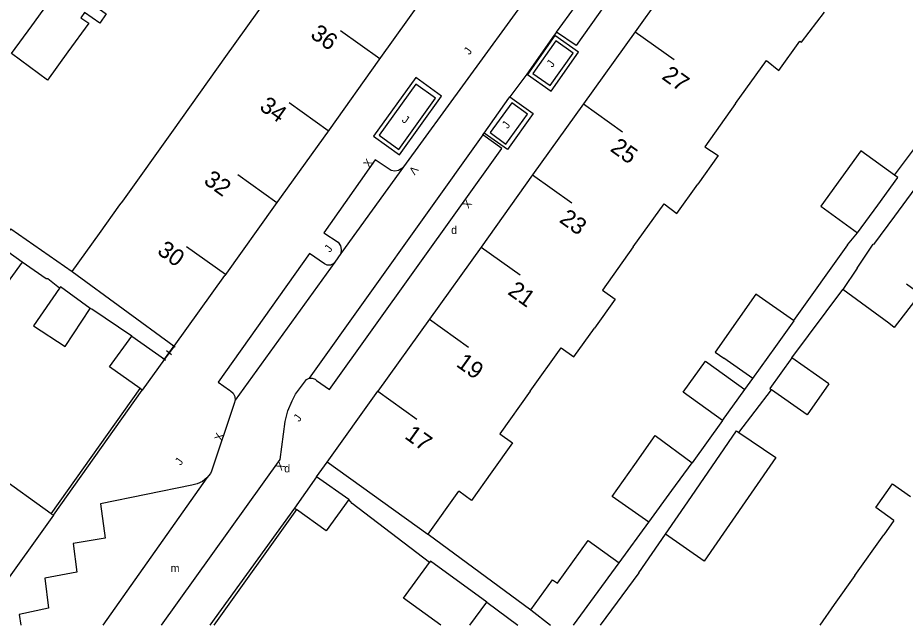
# Model space of a CAD drawing. Extents: x 134999 to 136502, y 457398 to 459002.
# Drawn here: x 135503.6 to 135559.1, y 457400 to 457437.9 of the extents above; entities that cross this region are included whole.
import ezdxf

# ---------------------------------------------------------------- set-up
doc = ezdxf.new("R2010")
doc.units = 0
for name, color, linetype in [('RI_DGTB_15', 7, 'Continuous'), ('RI_DGTB_23', 7, 'Continuous'), ('RI_DGTB_29', 7, 'Continuous'), ('RI_DGTB_30', 7, 'Continuous'), ('RI_DGTB_31', 7, 'Continuous'), ('RI_DGTB_35', 7, 'Continuous'), ('RI_DGTB_36', 7, 'Continuous'), ('RI_DGTB_4', 7, 'Continuous'), ('RI_DGTB_43', 7, 'Continuous'), ('RI_DGTB_48', 7, 'Continuous'), ('RI_DGTB_5', 7, 'Continuous'), ('RI_DGTB_53', 7, 'Continuous'), ('RI_DGTB_54', 7, 'Continuous'), ('RI_DGTB_6', 7, 'Continuous')]:
    doc.layers.add(name, color=color, linetype=linetype)

msp = doc.modelspace()

# ---------------------------------------------------------------- linework, layer by layer
at = {"layer": 'RI_DGTB_15'}
for p, q in [((135526.23, 457435.375), (135523.79, 457437.12)), ((135542.188, 457437.075), (135544.628, 457435.33)), ((135523.021, 457430.884), (135520.581, 457432.629)), ((135538.967, 457432.573), (135541.407, 457430.828)), ((135519.812, 457426.393), (135517.372, 457428.138)), ((135535.787, 457428.129), (135538.227, 457426.384)), ((135516.603, 457421.902), (135514.163, 457423.647)), ((135516.603, 457421.902), (135514.163, 457423.647)), ((135532.565, 457423.626), (135535.005, 457421.881)), ((135529.343, 457419.123), (135531.783, 457417.378)), ((135526.121, 457414.62), (135528.561, 457412.875))]:
    msp.add_line(p, q, dxfattribs=at)
at = {"layer": 'RI_DGTB_23'}
for p, q in [((135512.787, 457416.621), (135513.397, 457417.422)), ((135522.287, 457409.263), (135522.95, 457410.187))]:
    msp.add_line(p, q, dxfattribs=at)
at = {"layer": 'RI_DGTB_31'}
for p, q in [((135532.763, 457430.737), (135534.301, 457432.915)), ((135534.301, 457432.915), (135534.363, 457433.003))]:
    msp.add_line(p, q, dxfattribs=at)
for points in [[(135535.462, 457434.407), (135536.941, 457433.364), (135538.659, 457435.797), (135537.179, 457436.84), (135535.462, 457434.407)], [(135535.804, 457434.466), (135536.882, 457433.706), (135538.316, 457435.738), (135537.238, 457436.498), (135535.804, 457434.466)], [(135534.363, 457433.003), (135535.822, 457431.972), (135534.219, 457429.708), (135532.763, 457430.737)]]:
    msp.add_lwpolyline(points, dxfattribs=at)
for points in [[(135525.844, 457430.543), (135527.459, 457429.382), (135530.1, 457433.057), (135528.484, 457434.218)], [(135526.194, 457430.607), (135527.432, 457429.719), (135529.725, 457432.917), (135528.487, 457433.805)], [(135533.125, 457430.772), (135534.113, 457430.054), (135535.47, 457431.92), (135534.482, 457432.638)]]:
    msp.add_lwpolyline(points, close=True, dxfattribs=at)
at = {"layer": 'RI_DGTB_4'}
for p, q in [((135545.483, 457441.681), (135542.188, 457437.075)), ((135529.437, 457439.868), (135526.186, 457435.319)), ((135542.188, 457437.075), (135538.967, 457432.573)), ((135526.186, 457435.319), (135523.065, 457430.951)), ((135538.967, 457432.573), (135535.784, 457428.125)), ((135523.065, 457430.951), (135519.71, 457426.256)), ((135535.784, 457428.125), (135532.565, 457423.626)), ((135519.71, 457426.256), (135516.561, 457421.85)), ((135507.02, 457422.089), (135508.717, 457424.462)), ((135532.565, 457423.626), (135529.343, 457419.123)), ((135507.02, 457422.089), (135513.397, 457417.422)), ((135513.397, 457417.422), (135516.561, 457421.85)), ((135529.343, 457419.123), (135526.121, 457414.62)), ((135529.262, 457405.696), (135531.182, 457408.383)), ((135505.842, 457406.869), (135501.241, 457400.435))]:
    msp.add_line(p, q, dxfattribs=at)
for points in [[(135522.95, 457410.187), (135526.121, 457414.62)], [(135529.262, 457405.696), (135529.236, 457405.66), (135522.95, 457410.187)]]:
    msp.add_lwpolyline(points, dxfattribs=at)
at = {"layer": 'RI_DGTB_48'}
for p, q in [((135513.379, 457417.443), (135512.758, 457416.615)), ((135513.397, 457417.422), (135512.787, 457416.621)), ((135513.296, 457417.505), (135513.462, 457417.381)), ((135512.675, 457416.677), (135512.841, 457416.553)), ((135512.903, 457417.153), (135513.234, 457416.905))]:
    msp.add_line(p, q, dxfattribs=at)
at = {"layer": 'RI_DGTB_5'}
for p, q in [((135516.628, 457435.527), (135519.734, 457439.872)), ((135552.594, 457436.415), (135554.027, 457438.286)), ((135513.34, 457430.928), (135516.628, 457435.527)), ((135510.174, 457426.5), (135513.34, 457430.928)), ((135508.717, 457424.462), (135509.997, 457426.253)), ((135509.997, 457426.253), (135510.174, 457426.5)), ((135505.71, 457406.962), (135501.718, 457409.812)), ((135505.71, 457406.962), (135505.842, 457406.869)), ((135555.909, 457403.105), (135557.72, 457405.645)), ((135555.909, 457403.105), (135554.636, 457401.296)), ((135554.636, 457401.296), (135553.724, 457400))]:
    msp.add_line(p, q, dxfattribs=at)
for points in [[(135548.472, 457432.584), (135550.395, 457435.276), (135551.172, 457434.657), (135552.49, 457436.494)], [(135552.49, 457436.494), (135552.594, 457436.415)], [(135548.472, 457432.584), (135546.549, 457429.893), (135547.37, 457429.342), (135546.105, 457427.557)], [(135542.076, 457423.632), (135543.998, 457426.322), (135544.799, 457425.715), (135546.105, 457427.557)], [(135542.076, 457423.632), (135540.151, 457420.938), (135540.942, 457420.367), (135539.648, 457418.56)], [(135535.638, 457414.621), (135537.566, 457417.319), (135538.366, 457416.769), (135539.648, 457418.56)], [(135535.638, 457414.621), (135533.738, 457411.961), (135534.524, 457411.387), (135533.246, 457409.586)], [(135533.246, 457409.586), (135531.969, 457407.785), (135531.182, 457408.383)], [(135558.359, 457406.552), (135557.229, 457407.347), (135558.276, 457408.835), (135559.406, 457408.04)], [(135558.359, 457406.552), (135557.72, 457405.645)]]:
    msp.add_lwpolyline(points, dxfattribs=at)
at = {"layer": 'RI_DGTB_53'}
for p, q in [((135537.288, 457437.052), (135540.711, 457441.792)), ((135532.684, 457430.625), (135521.821, 457415.426)), ((135527.712, 457428.631), (135523.805, 457423.216)), ((135523.424, 457422.67), (135517.204, 457414.066)), ((135515.43, 457409.202), (135508.939, 457400))]:
    msp.add_line(p, q, dxfattribs=at)
at = {"layer": 'RI_DGTB_54'}
for p, q in [((135536.405, 457440.579), (135527.712, 457428.631)), ((135532.763, 457430.737), (135534.301, 457432.915)), ((135534.301, 457432.915), (135534.363, 457433.003)), ((135532.684, 457430.625), (135532.763, 457430.737)), ((135503.176, 457424.758), (135507.02, 457422.089)), ((135555.453, 457423.772), (135556.09, 457424.513)), ((135555.453, 457423.772), (135552.092, 457419.039)), ((135523.805, 457423.216), (135523.424, 457422.67)), ((135551.974, 457416.712), (135555.164, 457420.965)), ((135505.71, 457406.962), (135511.257, 457414.78)), ((135505.842, 457406.869), (135511.389, 457414.687)), ((135548.68, 457412.044), (135550.714, 457414.709)), ((135547.658, 457412.78), (135545.762, 457410.142)), ((135520.902, 457407.323), (135515.616, 457400)), ((135521.032, 457407.23), (135515.862, 457400)), ((135529.262, 457405.696), (135535.68, 457400.973)), ((135542.415, 457403.268), (135540.014, 457400)), ((135532.931, 457401.441), (135534.857, 457400))]:
    msp.add_line(p, q, dxfattribs=at)
for points in [[(135540.711, 457441.792), (135540.669, 457441.579), (135540.707, 457441.364), (135540.8, 457441.201), (135541.607, 457440.599), (135538.508, 457436.206), (135537.288, 457437.052)], [(135537.288, 457437.052), (135537.141, 457436.856), (135535.429, 457434.43), (135534.363, 457433.003)], [(135558.397, 457428.12), (135561.834, 457432.704), (135562.419, 457433.383)], [(135521.821, 457415.426), (135522.012, 457415.435), (135522.19, 457415.367), (135522.287, 457415.282), (135523.088, 457414.72), (135533.872, 457429.769), (135532.684, 457430.625)], [(135527.712, 457428.631), (135527.608, 457428.525), (135527.407, 457428.412), (135527.18, 457428.373), (135526.953, 457428.414), (135526.753, 457428.53), (135525.952, 457429.064), (135522.745, 457424.512), (135523.633, 457423.933), (135523.644, 457423.92), (135523.774, 457423.707), (135523.829, 457423.464), (135523.805, 457423.216)], [(135523.424, 457422.67), (135523.327, 457422.576), (135523.151, 457422.498), (135522.958, 457422.498), (135522.782, 457422.575), (135521.843, 457423.217), (135516.134, 457415.187), (135516.838, 457414.687), (135516.916, 457414.644), (135517.08, 457414.49), (135517.18, 457414.289), (135517.204, 457414.066)], [(135505.401, 457421.628), (135503.896, 457422.688)], [(135506.232, 457421.061), (135505.501, 457421.631), (135505.401, 457421.628)], [(135510.736, 457418.061), (135508.241, 457419.751), (135508.134, 457419.79)], [(135512.605, 457400), (135520.02, 457410.346), (135520.318, 457412.721), (135520.499, 457413.385), (135520.757, 457414.024), (135520.972, 457414.437), (135521.531, 457415.192), (135521.651, 457415.34), (135521.821, 457415.426)], [(135549.049, 457414.717), (135549.547, 457415.41)], [(135517.204, 457414.066), (135517.149, 457413.848), (135515.733, 457409.628), (135515.651, 457409.479), (135515.43, 457409.202)], [(135515.43, 457409.202), (135515.153, 457408.982), (135514.834, 457408.829), (135514.488, 457408.751), (135508.78, 457407.587), (135509.072, 457405.442), (135507.084, 457405.096), (135507.319, 457403.31), (135505.312, 457402.932), (135505.547, 457401.075), (135503.698, 457400.681), (135503.81, 457400)], [(135529.335, 457403.92), (135524.521, 457407.611), (135524.295, 457407.849)], [(135541.191, 457403.902), (135543.052, 457406.443)], [(135542.415, 457403.268), (135544.089, 457405.697)]]:
    msp.add_lwpolyline(points, dxfattribs=at)
at = {"layer": 'RI_DGTB_6'}
for p, q in [((135503.896, 457422.688), (135502.121, 457420.246)), ((135558.044, 457418.861), (135555.164, 457420.965)), ((135510.736, 457418.061), (135512.787, 457416.621)), ((135549.547, 457415.41), (135547.725, 457416.686)), ((135554.297, 457415.075), (135551.974, 457416.712)), ((135512.787, 457416.621), (135511.389, 457414.687)), ((135547.248, 457416.012), (135549.049, 457414.717)), ((135511.389, 457414.687), (135511.257, 457414.78)), ((135543.052, 457406.443), (135540.758, 457408.052)), ((135520.902, 457407.323), (135521.032, 457407.23)), ((135546.507, 457404), (135544.089, 457405.697)), ((135539.255, 457405.292), (135541.191, 457403.902)), ((135531.858, 457400), (135532.931, 457401.441)), ((135535.68, 457400.973), (135536.905, 457400))]:
    msp.add_line(p, q, dxfattribs=at)
for points in [[(135507.756, 457441.945), (135509.273, 457440.896), (135507.966, 457439.008), (135509.148, 457438.19), (135508.752, 457437.617), (135507.797, 457438.278), (135507.563, 457437.94)], [(135504.493, 457437.452), (135505.756, 457439.191)], [(135507.563, 457437.94), (135508.053, 457437.601), (135506.754, 457435.81)], [(135503.23, 457435.712), (135504.493, 457437.452)], [(135506.754, 457435.81), (135505.48, 457434.052), (135503.23, 457435.712)], [(135558.397, 457428.12), (135556.303, 457429.64), (135555.047, 457427.912)], [(135555.047, 457427.912), (135553.79, 457426.183), (135556.09, 457424.513)], [(135557.346, 457426.24), (135558.603, 457427.97), (135558.397, 457428.12)], [(135559.676, 457427.286), (135558.387, 457425.545)], [(135556.09, 457424.513), (135557.346, 457426.24)], [(135558.387, 457425.545), (135557.082, 457423.782)], [(135503.896, 457422.688), (135502.454, 457423.704), (135503.176, 457424.758)], [(135556.065, 457422.314), (135557.058, 457423.8), (135557.082, 457423.782)], [(135556.065, 457422.314), (135555.164, 457420.965)], [(135506.232, 457421.061), (135504.596, 457418.697), (135506.587, 457417.416), (135508.134, 457419.79)], [(135508.134, 457419.79), (135506.282, 457421.133), (135506.232, 457421.061)], [(135559.149, 457421.321), (135559.99, 457420.701), (135558.383, 457418.601), (135558.044, 457418.861)], [(135552.092, 457419.039), (135549.734, 457420.69), (135548.607, 457419.085)], [(135548.607, 457419.085), (135547.189, 457417.065), (135547.725, 457416.686)], [(135550.984, 457417.41), (135552.133, 457419.009), (135552.092, 457419.039)], [(135511.257, 457414.78), (135509.351, 457416.135), (135510.736, 457418.061)], [(135549.547, 457415.41), (135550.984, 457417.41)], [(135551.974, 457416.712), (135550.61, 457414.783), (135550.714, 457414.709)], [(135547.658, 457412.78), (135545.2, 457414.555), (135546.587, 457416.486), (135547.248, 457416.012)], [(135554.297, 457415.075), (135552.93, 457413.143), (135550.714, 457414.709)], [(135547.658, 457412.78), (135549.049, 457414.717)], [(135542.165, 457410.043), (135543.439, 457411.845), (135545.762, 457410.142)], [(135545.481, 457407.718), (135548.531, 457412.145), (135548.68, 457412.044)], [(135548.68, 457412.044), (135550.972, 457410.481), (135547.899, 457406.021)], [(135540.758, 457408.052), (135542.165, 457410.043)], [(135544.493, 457408.41), (135545.762, 457410.142)], [(135522.287, 457409.263), (135520.902, 457407.323)], [(135524.295, 457407.849), (135522.287, 457409.263)], [(135543.052, 457406.443), (135544.493, 457408.41)], [(135524.295, 457407.849), (135522.891, 457405.903), (135521.032, 457407.23)], [(135544.089, 457405.697), (135545.481, 457407.718)], [(135547.899, 457406.021), (135546.507, 457404)], [(135535.68, 457400.973), (135537.023, 457402.841), (135537.332, 457402.619), (135539.255, 457405.292)], [(135530.051, 457400), (135527.712, 457401.692), (135529.335, 457403.92)], [(135532.931, 457401.441), (135529.402, 457404.012), (135529.335, 457403.92)], [(135538.332, 457400), (135541.191, 457403.902)]]:
    msp.add_lwpolyline(points, dxfattribs=at)

# ---------------------------------------------------------------- texts
at = {"layer": 'RI_DGTB_29'}
for p in [(135530.695, 457424.44), (135520.267, 457409.552)]:
    msp.add_text('d', height=0.5, dxfattribs=at).set_placement(p)
at = {"layer": 'RI_DGTB_30'}
for s, height, rotation, p in [('X', 0.499, 54.8344, (135525.571, 457428.544)), ('V', 0.499, 232.4765, (135528.294, 457428.742)), ('X', 0.499, 232.4765, (135531.642, 457426.643)), ('X', 0.5, 71.4473, (135516.358, 457411.487)), ('X', 0.499, 232.4765, (135519.961, 457410.269))]:
    msp.add_text(s, height=height, rotation=rotation, dxfattribs=at).set_placement(p)
at = {"layer": 'RI_DGTB_31'}
for height, rotation, p in [(0.499, 54.4415, (135531.844, 457435.593)), (0.499, 54.4463, (135537.017, 457434.801)), (0.5, 325.5704, (135527.573, 457431.483)), (0.499, 54.4415, (135534.229, 457430.976)), (0.499, 54.4415, (135523.127, 457423.25)), (0.499, 54.4415, (135521.203, 457412.669)), (0.499, 54.4415, (135513.798, 457409.947))]:
    msp.add_text('J', height=height, rotation=rotation, dxfattribs=at).set_placement(p)
at = {"layer": 'RI_DGTB_35'}
for s, rotation, p in [('30', 324.4462, (135512.268, 457423.245)), ('17', 324.4141, (135527.73, 457411.714))]:
    msp.add_text(s, height=1.054, rotation=rotation, dxfattribs=at).set_placement(p)
at = {"layer": 'RI_DGTB_36'}
for s, rotation, p in [('36', 324.4462, (135521.835, 457436.761)), ('27', 324.4141, (135543.797, 457434.169)), ('34', 324.4462, (135518.653, 457432.251)), ('25', 324.4141, (135540.576, 457429.666)), ('32', 324.4462, (135515.172, 457427.64)), ('23', 324.4141, (135537.396, 457425.224)), ('21', 324.4141, (135534.174, 457420.72)), ('19', 324.4141, (135530.952, 457416.217))]:
    msp.add_text(s, height=1.054, rotation=rotation, dxfattribs=at).set_placement(p)
at = {"layer": 'RI_DGTB_43'}
msp.add_text('m', height=0.5, dxfattribs=at).set_placement((135513.166, 457403.322))

doc.saveas('drawing.dxf')
